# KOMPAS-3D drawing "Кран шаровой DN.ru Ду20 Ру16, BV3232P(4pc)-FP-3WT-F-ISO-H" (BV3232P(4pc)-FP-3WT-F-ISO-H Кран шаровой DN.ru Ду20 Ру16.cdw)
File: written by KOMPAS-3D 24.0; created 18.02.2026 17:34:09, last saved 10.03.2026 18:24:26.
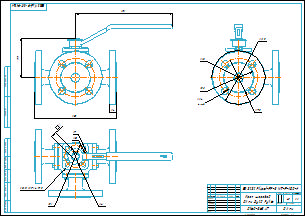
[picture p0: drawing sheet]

Document properties: Автор: R2D2; Форматы листов документа: A2; Полное имя файла: BV3232P(4pc)-FP-3WT-F-ISO-H Кран шаровой DN.ru Ду20 Ру16.m3d; Масса: 4.5; Наименование: Кран шаровой DN.ru Ду20 Ру16; Количество листов документа: 1; Примечание: D160-36347

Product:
- Part/product: Кран шаровой DN.ru Ду20 Ру16  | designation BV3232P(4pc)-FP-3WT-F-ISO-H
    Масса: 4.5
    Раздел спецификации: Прочие изделия
    Примечание: D160-36347

Views: Вид 1, Спереди, Проекционный вид 2
Referenced files in E:\Работа\Зайцев\BV3232P(4pc)-FP-3WL-F-ISO-H Кран шаровой DN.ru Ду15-100 Ру16\DN20\: BV3232P(4pc)-FP-3WL-F-ISO-H Кран шаровой DN.ru Ду20 Ру16.m3d
Referenced files in E:\Работа\Зайцев\BV3232P(4pc)-FP-3WT-F-ISO-H Кран шаровой DN.ru Ду15-100 Ру16\DN20\: BV3232P(4pc)-FP-3WT-F-ISO-H Кран шаровой DN.ru Ду20 Ру16.m3d
Referenced files in E:\Работа\Зайцев\Для компаса\: чертеж DN.ru А3.cdt
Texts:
  BV3232P(4pc)-FP-3WT-F-ISO-H
  чертеж DN.ru А3.cdt
  Кран шаровой
  DN.ru Ду20 Ру16
  Кран шаровой DN.ru Ду20 Ру16
  BV3232P(4pc)-FP-3WT-F-ISO-H Кран шаровой DN.ru Ду20 Ру16
Dimensions and other numbers on the sheet: 0; 3; 2; 4; 160; 14; 77; 190; 105; 75; 58; 18; 4 отв.; 1:1; 1; 4,5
